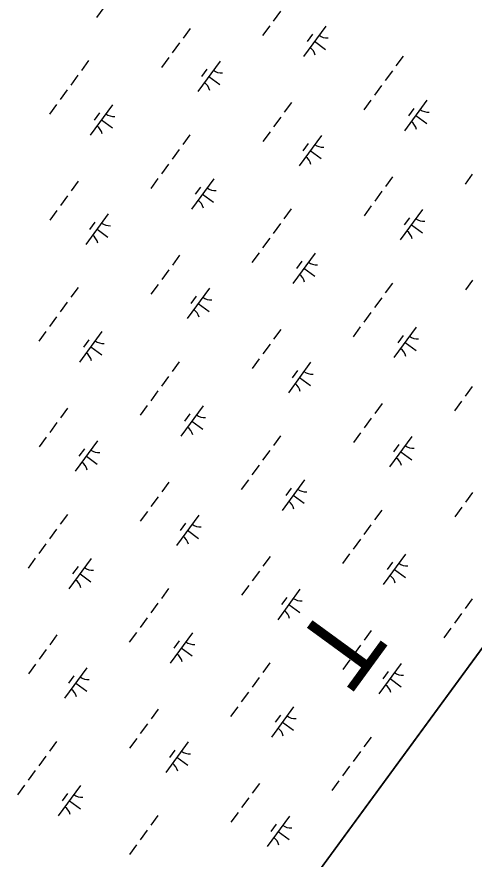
# Model space of a CAD drawing. Extents: x 3905714 to 3926767, y 183354 to 205755.
# Drawn here: x 3920164 to 3920770, y 191904 to 193020 of the extents above; entities that cross this region are included whole.
import ezdxf

# ---------------------------------------------------------------- set-up
doc = ezdxf.new("R2010")
doc.units = 0
for name, color, linetype in [('V-GRID-FRAM', 7, 'Continuous'), ('V-RIVR-IDEN', 7, 'Continuous'), ('V-WETL-SWMP', 7, 'Continuous')]:
    doc.layers.add(name, color=color, linetype=linetype)

msp = doc.modelspace()

# ---------------------------------------------------------------- linework, layer by layer
at = {"layer": 'V-GRID-FRAM'}
msp.add_lwpolyline([(3924287.8, 196971.1), (3915521.4, 185005.6), (3909313.3, 189695.8), (3918205.9, 201877.9), (3924287.8, 196971.1)], dxfattribs=at)
at = {"layer": 'V-WETL-SWMP'}
for p, q in [((3919501.5, 190438.1), (3921562.2, 193250.8)), ((3920298.9, 193059.7), (3920269.4, 193019.4)), ((3920513.1, 193027.6), (3920503.6, 193014.7)), ((3920393.5, 193005), (3920384, 192992.1)), ((3920498.9, 193008.3), (3920489.4, 192995.4)), ((3920573.1, 193007.9), (3920543.5, 192967.6)), ((3920555.6, 192997.2), (3920548.5, 192987.5)), ((3920379.3, 192985.6), (3920369.8, 192972.7)), ((3920558.3, 192987.8), (3920572.8, 192977.1)), ((3920675.6, 192968), (3920666.1, 192955.1)), ((3920258.9, 192962.2), (3920249.5, 192949.3)), ((3920365.1, 192966.3), (3920355.6, 192953.3)), ((3920433.1, 192961.4), (3920403.5, 192921.1)), ((3920415.6, 192950.7), (3920408.6, 192941)), ((3920661.4, 192948.7), (3920652, 192935.8)), ((3920244.7, 192942.9), (3920235.3, 192929.9)), ((3920418.3, 192941.3), (3920432.8, 192930.6)), ((3920230.6, 192923.5), (3920221.1, 192910.6)), ((3920647.2, 192929.3), (3920637.8, 192916.4)), ((3920216.4, 192904.1), (3920206.9, 192891.2)), ((3920290.6, 192903.8), (3920261, 192863.5)), ((3920527.6, 192906.7), (3920518.2, 192893.8)), ((3920633, 192910), (3920623.6, 192897.1)), ((3920707.2, 192909.6), (3920677.7, 192869.3)), ((3920273.1, 192893), (3920266, 192883.4)), ((3920689.8, 192898.9), (3920682.7, 192889.2)), ((3920692.5, 192889.5), (3920707, 192878.8)), ((3920275.8, 192883.6), (3920290.3, 192873)), ((3920513.5, 192887.3), (3920504, 192874.4)), ((3920499.3, 192867.9), (3920489.8, 192855)), ((3920393.1, 192863.9), (3920383.7, 192851)), ((3920567.3, 192863.1), (3920537.7, 192822.8)), ((3920378.9, 192844.5), (3920369.5, 192831.6)), ((3920549.8, 192852.4), (3920542.7, 192842.7)), ((3920552.5, 192843), (3920567, 192832.3)), ((3920364.7, 192825.2), (3920355.3, 192812.3)), ((3920767.2, 192811.7), (3920757.8, 192798.7)), ((3920245.1, 192802.5), (3920235.7, 192789.6)), ((3920350.6, 192805.8), (3920341.1, 192792.9)), ((3920424.7, 192805.5), (3920395.2, 192765.2)), ((3920661.8, 192808.4), (3920652.4, 192795.5)), ((3920407.3, 192794.7), (3920400.2, 192785.1)), ((3920647.6, 192789), (3920638.2, 192776.1)), ((3920231, 192783.2), (3920221.5, 192770.3)), ((3920410, 192785.3), (3920424.5, 192774.7)), ((3920527.3, 192765.6), (3920517.8, 192752.7)), ((3920633.4, 192769.6), (3920624, 192756.7)), ((3920216.8, 192763.8), (3920207.3, 192750.9)), ((3920284.8, 192759), (3920255.2, 192718.7)), ((3920701.5, 192764.8), (3920671.9, 192724.5)), ((3920267.3, 192748.2), (3920260.2, 192738.5)), ((3920513.1, 192746.2), (3920503.6, 192733.3)), ((3920684, 192754), (3920676.9, 192744.4)), ((3920686.7, 192744.6), (3920701.2, 192734)), ((3920270, 192738.8), (3920284.5, 192728.2)), ((3920498.9, 192726.9), (3920489.5, 192714)), ((3920379.3, 192704.2), (3920369.9, 192691.3)), ((3920484.7, 192707.5), (3920475.3, 192694.6)), ((3920558.9, 192707.2), (3920529.4, 192666.9)), ((3920541.5, 192696.4), (3920534.4, 192686.7)), ((3920365.1, 192684.9), (3920355.7, 192672)), ((3920544.1, 192687), (3920558.7, 192676.4)), ((3920351, 192665.5), (3920341.5, 192652.6)), ((3920661.5, 192667.3), (3920652, 192654.4)), ((3920767.6, 192671.3), (3920758.2, 192658.4)), ((3920244.8, 192661.5), (3920235.3, 192648.6)), ((3920419, 192660.7), (3920389.4, 192620.3)), ((3920401.5, 192649.9), (3920394.4, 192640.2)), ((3920647.3, 192647.9), (3920637.8, 192635)), ((3920230.6, 192642.1), (3920221.2, 192629.2)), ((3920404.2, 192640.5), (3920418.7, 192629.9)), ((3920216.4, 192622.8), (3920207, 192609.8)), ((3920633.1, 192628.6), (3920623.6, 192615.7)), ((3920618.9, 192609.2), (3920609.5, 192596.3)), ((3920202.2, 192603.4), (3920192.8, 192590.5)), ((3920276.4, 192603.1), (3920246.9, 192562.7)), ((3920513.5, 192605.9), (3920504, 192593)), ((3920693.1, 192608.9), (3920663.5, 192568.6)), ((3920675.6, 192598.1), (3920668.6, 192588.4)), ((3920259, 192592.3), (3920251.9, 192582.6)), ((3920678.3, 192588.7), (3920692.8, 192578.1)), ((3920261.6, 192582.9), (3920276.2, 192572.3)), ((3920499.3, 192586.6), (3920489.9, 192573.7)), ((3920485.1, 192567.2), (3920475.7, 192554.3)), ((3920379, 192563.2), (3920369.5, 192550.3)), ((3920553.1, 192562.4), (3920523.6, 192522)), ((3920364.8, 192543.8), (3920355.3, 192530.9)), ((3920535.7, 192551.6), (3920528.6, 192541.9)), ((3920538.4, 192542.2), (3920552.9, 192531.6)), ((3920350.6, 192524.4), (3920341.1, 192511.5)), ((3920767.3, 192530.3), (3920757.8, 192517.4)), ((3920753.1, 192510.9), (3920743.6, 192498)), ((3920231, 192501.8), (3920221.6, 192488.9)), ((3920336.4, 192505.1), (3920327, 192492.2)), ((3920410.6, 192504.8), (3920381.1, 192464.4)), ((3920647.7, 192507.6), (3920638.2, 192494.7)), ((3920393.1, 192494), (3920386.1, 192484.3)), ((3920633.5, 192488.3), (3920624, 192475.4)), ((3920216.8, 192482.4), (3920207.4, 192469.5)), ((3920395.8, 192484.6), (3920410.3, 192474)), ((3920513.2, 192464.9), (3920503.7, 192452)), ((3920619.3, 192468.9), (3920609.9, 192456)), ((3920687.3, 192464.1), (3920657.8, 192423.7)), ((3920202.6, 192463.1), (3920193.2, 192450.2)), ((3920270.6, 192458.2), (3920241.1, 192417.9)), ((3920669.9, 192453.3), (3920662.8, 192443.6)), ((3920253.2, 192447.5), (3920246.1, 192437.8)), ((3920499, 192445.5), (3920489.5, 192432.6)), ((3920672.5, 192443.9), (3920687.1, 192433.3)), ((3920255.9, 192438.1), (3920270.4, 192427.4)), ((3920484.8, 192426.1), (3920475.3, 192413.2)), ((3920365.2, 192403.5), (3920355.7, 192390.6)), ((3920470.6, 192406.8), (3920461.1, 192393.9)), ((3920544.8, 192406.5), (3920515.2, 192366.1)), ((3920527.3, 192395.7), (3920520.2, 192386)), ((3920530, 192386.3), (3920544.5, 192375.6)), ((3920767.7, 192390), (3920758.2, 192377)), ((3920351, 192384.1), (3920341.5, 192371.2)), ((3920336.8, 192364.8), (3920327.4, 192351.9)), ((3920647.3, 192366.6), (3920637.9, 192353.6)), ((3920753.5, 192370.6), (3920744, 192357.7)), ((3920230.7, 192360.7), (3920221.2, 192347.8)), ((3920404.8, 192359.9), (3920375.3, 192319.6)), ((3920216.5, 192341.4), (3920207, 192328.5)), ((3920387.4, 192349.2), (3920380.3, 192339.5)), ((3920633.1, 192347.2), (3920623.7, 192334.3)), ((3920390.1, 192339.8), (3920404.6, 192329.1)), ((3920202.3, 192322), (3920192.8, 192309.1)), ((3920619, 192327.8), (3920609.5, 192314.9)), ((3920604.8, 192308.5), (3920595.3, 192295.6)), ((3920679, 192308.1), (3920649.4, 192267.8)), ((3920188.1, 192302.6), (3920178.6, 192289.7)), ((3920262.3, 192302.3), (3920232.7, 192262)), ((3920499.4, 192305.2), (3920489.9, 192292.3)), ((3920661.5, 192297.4), (3920654.4, 192287.7)), ((3920244.8, 192291.6), (3920237.7, 192281.9)), ((3920485.2, 192285.8), (3920475.7, 192272.9)), ((3920664.2, 192288), (3920678.7, 192277.3)), ((3920247.5, 192282.2), (3920262, 192271.5)), ((3920471, 192266.5), (3920461.5, 192253.6)), ((3920364.8, 192262.4), (3920355.4, 192249.5)), ((3920539, 192261.6), (3920509.5, 192221.3)), ((3920350.7, 192243.1), (3920341.2, 192230.2)), ((3920521.6, 192250.9), (3920514.5, 192241.2)), ((3920524.2, 192241.5), (3920538.8, 192230.8)), ((3920767.3, 192248.9), (3920757.9, 192236)), ((3920336.5, 192223.7), (3920327, 192210.8)), ((3920753.1, 192229.5), (3920743.7, 192216.6)), ((3920739, 192210.2), (3920729.5, 192197.3)), ((3920216.9, 192201.1), (3920207.4, 192188.1)), ((3920322.3, 192204.3), (3920312.8, 192191.4)), ((3920396.5, 192204), (3920366.9, 192163.7)), ((3920633.5, 192206.9), (3920624.1, 192194)), ((3920379, 192193.2), (3920371.9, 192183.6)), ((3920619.4, 192187.5), (3920609.9, 192174.6)), ((3920202.7, 192181.7), (3920193.2, 192168.8)), ((3920381.7, 192183.8), (3920396.2, 192173.2)), ((3920499, 192164.1), (3920489.6, 192151.2)), ((3920605.2, 192168.2), (3920595.7, 192155.3)), ((3920673.2, 192163.3), (3920643.6, 192123)), ((3920188.5, 192162.3), (3920179, 192149.4)), ((3920256.5, 192157.5), (3920227, 192117.2)), ((3920655.7, 192152.6), (3920648.6, 192142.9)), ((3920239.1, 192146.7), (3920232, 192137.1)), ((3920484.8, 192144.8), (3920475.4, 192131.9)), ((3920658.4, 192143.2), (3920672.9, 192132.5)), ((3920241.7, 192137.3), (3920256.3, 192126.7)), ((3920470.6, 192125.4), (3920461.2, 192112.5)), ((3920351.1, 192102.7), (3920341.6, 192089.8)), ((3920456.5, 192106), (3920447, 192093.1)), ((3920530.6, 192105.7), (3920501.1, 192065.4)), ((3920513.2, 192094.9), (3920506.1, 192085.3)), ((3920515.9, 192085.5), (3920530.4, 192074.9)), ((3920336.9, 192083.4), (3920327.4, 192070.5)), ((3920322.7, 192064), (3920313.2, 192051.1)), ((3920633.2, 192065.8), (3920623.7, 192052.9)), ((3920216.5, 192060), (3920207.1, 192047.1)), ((3920390.7, 192059.2), (3920361.1, 192018.9)), ((3920202.3, 192040.6), (3920192.9, 192027.7)), ((3920373.2, 192048.4), (3920366.1, 192038.7)), ((3920619, 192046.5), (3920609.6, 192033.5)), ((3920375.9, 192039), (3920390.4, 192028.4)), ((3920188.2, 192021.3), (3920178.7, 192008.4)), ((3920604.8, 192027.1), (3920595.4, 192014.2)), ((3920590.6, 192007.7), (3920581.2, 191994.8)), ((3920174, 192001.9), (3920164.5, 191989)), ((3920248.2, 192001.6), (3920218.6, 191961.2)), ((3920485.2, 192004.4), (3920475.8, 191991.5)), ((3920230.7, 191990.8), (3920223.6, 191981.1)), ((3920471, 191985.1), (3920461.6, 191972.2)), ((3920233.4, 191981.4), (3920247.9, 191970.8)), ((3920350.7, 191961.7), (3920341.2, 191948.8)), ((3920456.9, 191965.7), (3920447.4, 191952.8)), ((3920524.9, 191960.9), (3920495.3, 191920.6)), ((3920336.5, 191942.3), (3920327.1, 191929.4)), ((3920507.4, 191950.1), (3920500.3, 191940.4)), ((3920510.1, 191940.7), (3920524.6, 191930.1)), ((3920322.3, 191923), (3920312.9, 191910.1))]:
    msp.add_line(p, q, dxfattribs=at)
for centre, start, end in [((3920574.8, 193009.9), 233, 274.5436), ((3920542.1, 192965.3), 13, 54.5436), ((3920434.8, 192963.4), 233, 274.5436), ((3920402.2, 192918.8), 13, 54.5436), ((3920292.3, 192905.8), 233, 274.5436), ((3920709, 192911.6), 233, 274.5436), ((3920676.3, 192867), 13, 54.5436), ((3920259.7, 192861.2), 13, 54.5436), ((3920569, 192865.1), 233, 274.5436), ((3920536.4, 192820.5), 13, 54.5436), ((3920426.5, 192807.5), 233, 274.5436), ((3920393.8, 192762.9), 13, 54.5436), ((3920286.5, 192761), 233, 274.5436), ((3920703.2, 192766.8), 233, 274.5436), ((3920670.5, 192722.2), 13, 54.5436), ((3920253.9, 192716.4), 13, 54.5436), ((3920560.7, 192709.2), 233, 274.5436), ((3920528, 192664.6), 13, 54.5436), ((3920420.7, 192662.7), 233, 274.5436), ((3920388.1, 192618.1), 13, 54.5436), ((3920278.2, 192605), 233, 274.5436), ((3920694.8, 192610.9), 233, 274.5436), ((3920662.2, 192566.3), 13, 54.5436), ((3920245.5, 192560.5), 13, 54.5436), ((3920554.9, 192564.3), 233, 274.5436), ((3920522.2, 192519.8), 13, 54.5436), ((3920412.3, 192506.7), 233, 274.5436), ((3920379.7, 192462.2), 13, 54.5436), ((3920272.4, 192460.2), 233, 274.5436), ((3920689.1, 192466), 233, 274.5436), ((3920656.4, 192421.5), 13, 54.5436), ((3920239.7, 192415.7), 13, 54.5436), ((3920546.5, 192408.4), 233, 274.5436), ((3920513.9, 192363.9), 13, 54.5436), ((3920406.6, 192361.9), 233, 274.5436), ((3920373.9, 192317.3), 13, 54.5436), ((3920264, 192304.3), 233, 274.5436), ((3920680.7, 192310.1), 233, 274.5436), ((3920648.1, 192265.6), 13, 54.5436), ((3920231.4, 192259.7), 13, 54.5436), ((3920540.7, 192263.6), 233, 274.5436), ((3920508.1, 192219), 13, 54.5436), ((3920398.2, 192206), 233, 274.5436), ((3920365.6, 192161.4), 13, 54.5436), ((3920258.3, 192159.5), 233, 274.5436), ((3920674.9, 192165.3), 233, 274.5436), ((3920225.6, 192114.9), 13, 54.5436), ((3920642.3, 192120.7), 13, 54.5436), ((3920532.4, 192107.7), 233, 274.5436), ((3920499.7, 192063.1), 13, 54.5436), ((3920392.4, 192061.2), 233, 274.5436), ((3920359.8, 192016.6), 13, 54.5436), ((3920249.9, 192003.6), 233, 274.5436), ((3920217.2, 191959), 13, 54.5436), ((3920526.6, 191962.9), 233, 274.5436), ((3920494, 191918.3), 13, 54.5436)]:
    msp.add_arc(centre, 17.6, start, end, dxfattribs=at)

# ---------------------------------------------------------------- texts
at = {"layer": 'V-RIVR-IDEN'}
msp.add_text('T', height=100, rotation=233.8714, dxfattribs=at).set_placement((3920575.9, 192248.5))

doc.saveas('drawing.dxf')
